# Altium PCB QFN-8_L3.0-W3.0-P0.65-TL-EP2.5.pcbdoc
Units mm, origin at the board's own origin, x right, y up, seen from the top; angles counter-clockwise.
Board outline 16.43 x 15.85 mm, 2 copper layers (Top Layer, Bottom Layer), stack 0 mm thick; 1 components, 0 nets, 9 pads, 0 vias.
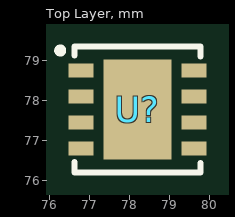
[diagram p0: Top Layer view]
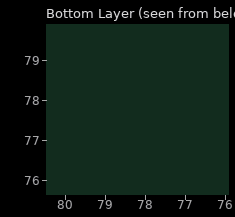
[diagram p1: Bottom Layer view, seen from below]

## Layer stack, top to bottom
Top Layer: signal copper (thickness not stored)
Bottom Layer: signal copper (thickness not stored)

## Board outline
86.28,69.85 69.85,69.85 69.85,85.702 86.28,85.702

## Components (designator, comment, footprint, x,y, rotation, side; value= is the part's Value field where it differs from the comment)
U? "" QFN-8_L3.0-W3.0-P0.65-TL-EP2.5 78.205,77.776 r0 top

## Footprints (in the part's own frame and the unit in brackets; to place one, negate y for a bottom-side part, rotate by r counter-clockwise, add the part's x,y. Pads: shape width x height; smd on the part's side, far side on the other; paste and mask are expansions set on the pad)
QFN-8_L3.0-W3.0-P0.65-TL-EP2.5 [mm]
  rect 0.625x0.35 smd paste+0 mask+0.05: 1(-1.412,0.975) 2(-1.412,0.325) 3(-1.412,-0.325) 4(-1.412,-0.975) 5(1.412,-0.975) 6(1.412,-0.325) 7(1.412,0.325) 8(1.412,0.975)
  rect 1.7x2.5 smd paste+0 mask+0.05: 9(0,0)
  silkscreen extent -2.01,-1.58 1.58,1.58

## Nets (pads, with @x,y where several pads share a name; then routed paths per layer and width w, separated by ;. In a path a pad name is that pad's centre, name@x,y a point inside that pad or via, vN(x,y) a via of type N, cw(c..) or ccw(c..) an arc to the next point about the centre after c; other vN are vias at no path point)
pads on no net: U?.1 U?.2 U?.3 U?.4 U?.5 U?.6 U?.7 U?.8 U?.9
